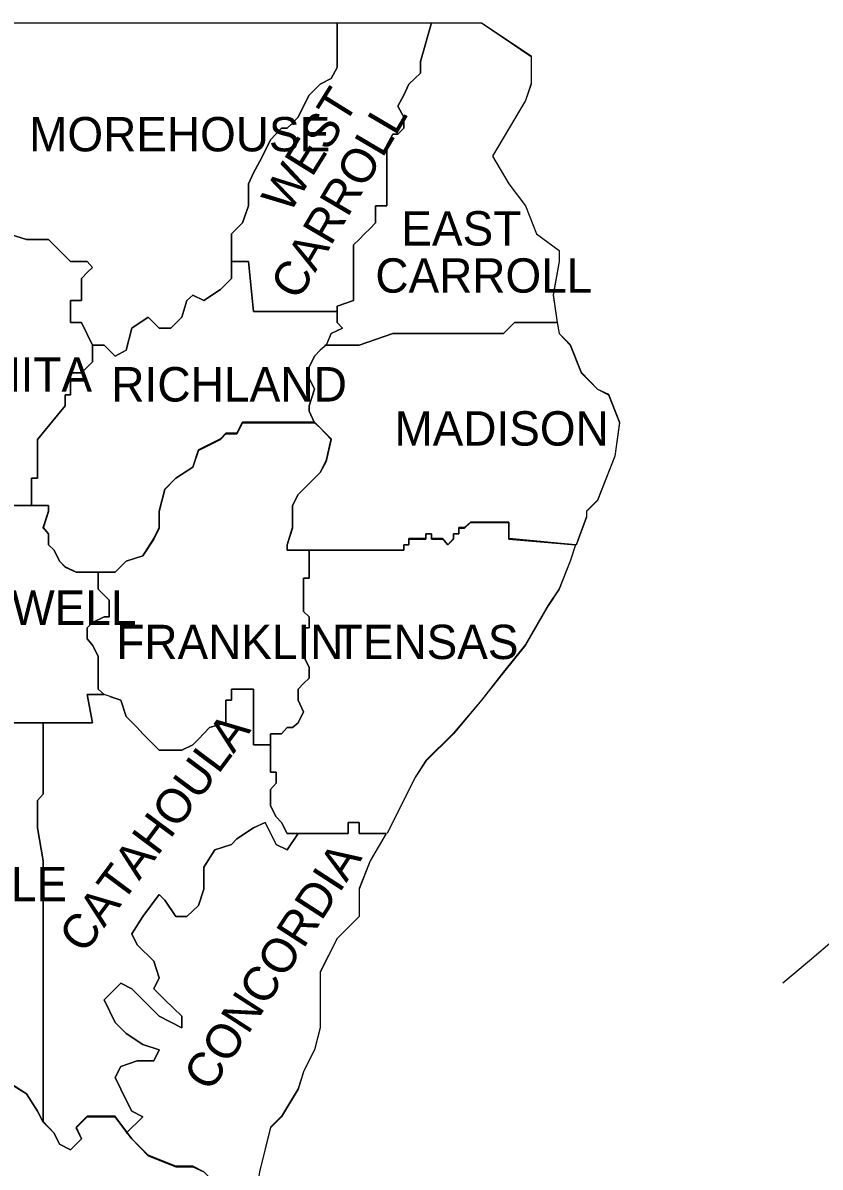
# Model space of a CAD drawing. Extents: x 0.23 to 2.82, y 0.04 to 1.79.
# Drawn here: x 2.3593 to 2.468, y 1.594 to 1.7498 of the extents above; entities that cross this region are included whole.
import ezdxf

# ---------------------------------------------------------------- set-up
doc = ezdxf.new("R2010")
doc.units = 0
for name, color, linetype in [('Annotation', 7, 'Continuous'), ('Dist05', 7, 'Continuous'), ('Dist08', 7, 'Continuous'), ('Dist58', 7, 'Continuous'), ('Standard Info', 7, 'Continuous')]:
    doc.layers.add(name, color=color, linetype=linetype)

msp = doc.modelspace()

# ---------------------------------------------------------------- linework, layer by layer
at = {"layer": 'Annotation'}
msp.add_open_spline([(2.54158, 1.68565), (2.52602, 1.64446), (2.46291, 1.61901), (2.54158, 1.68565), (2.46291, 1.61901)], degree=3, dxfattribs=at)
at = {"layer": 'Dist05'}
for p, q in [((2.35674, 1.74983), (2.40215, 1.74983)), ((2.40215, 1.74983), (2.41499, 1.74983)), ((2.41499, 1.74983), (2.42182, 1.74983))]:
    msp.add_line(p, q, dxfattribs=at)
for points in [[(2.42182, 1.74983), (2.42857, 1.74533), (2.42857, 1.74158), (2.42782, 1.73925), (2.42332, 1.73167), (2.42557, 1.72792), (2.42782, 1.72492), (2.42932, 1.72108), (2.4324, 1.71883), (2.4324, 1.71733), (2.43157, 1.71283), (2.43215, 1.709)], [(2.43215, 1.709), (2.4324, 1.7075), (2.4339, 1.706), (2.4354, 1.70225), (2.43765, 1.69992), (2.43915, 1.69925), (2.44065, 1.69542), (2.43999, 1.69083), (2.43765, 1.68483), (2.43615, 1.68333), (2.43615, 1.68258), (2.43474, 1.67875)], [(2.39907, 1.69542), (2.38924, 1.69542), (2.38849, 1.69392), (2.38699, 1.69392), (2.38624, 1.69317), (2.38324, 1.69167), (2.38249, 1.68933), (2.38015, 1.68783), (2.37865, 1.68633), (2.3779, 1.68333), (2.3779, 1.68108), (2.37715, 1.67958), (2.37565, 1.67725), (2.3734, 1.6765), (2.3719, 1.675), (2.36957, 1.675), (2.36807, 1.675), (2.36657, 1.675), (2.36507, 1.67575), (2.36432, 1.6765), (2.36357, 1.678), (2.36282, 1.67875), (2.36282, 1.68025), (2.36207, 1.68108), (2.36282, 1.68333), (2.36282, 1.68408), (2.36049, 1.68408)], [(2.41124, 1.678), (2.39532, 1.678), (2.39532, 1.67875), (2.39607, 1.68108), (2.39607, 1.68258), (2.39607, 1.68408), (2.39682, 1.68558), (2.39982, 1.68858), (2.40065, 1.69017), (2.40132, 1.69317), (2.39982, 1.69467), (2.39907, 1.69542)], [(2.36049, 1.68408), (2.35524, 1.68408), (2.35449, 1.68333), (2.3514, 1.68333), (2.35074, 1.68408), (2.34015, 1.68408)], [(2.42557, 1.67958), (2.42557, 1.68183), (2.42032, 1.68183), (2.41949, 1.68108), (2.41874, 1.68108), (2.41874, 1.68025), (2.41799, 1.68025), (2.41799, 1.67958), (2.41724, 1.67875), (2.41649, 1.67958), (2.41499, 1.67958), (2.41499, 1.68025), (2.41424, 1.68025), (2.41424, 1.67958), (2.4119, 1.67958), (2.4119, 1.67875), (2.41124, 1.67875), (2.41124, 1.678)], [(2.43465, 1.67875), (2.42557, 1.67958)]]:
    msp.add_lwpolyline(points, dxfattribs=at)
at = {"layer": 'Dist08'}
for points in [[(2.36207, 1.60008), (2.36132, 1.60167), (2.35982, 1.60392), (2.35749, 1.60542), (2.35524, 1.60617), (2.35299, 1.6085), (2.3514, 1.61225), (2.3499, 1.61525), (2.3469, 1.61675), (2.3439, 1.61908), (2.34165, 1.62133), (2.34082, 1.62358), (2.33932, 1.62583), (2.33707, 1.62808), (2.33632, 1.62883), (2.33557, 1.63192), (2.33632, 1.63417), (2.33632, 1.63717), (2.33707, 1.64092), (2.33757, 1.644)], [(2.37349, 1.59875), (2.3719, 1.60092), (2.36807, 1.60092), (2.36657, 1.59942), (2.36732, 1.59783), (2.36582, 1.59633), (2.36432, 1.59708), (2.36357, 1.59858), (2.36207, 1.60017)], [(2.38057, 1.57817), (2.38249, 1.582), (2.38399, 1.5835), (2.38399, 1.5865), (2.38474, 1.5895), (2.38549, 1.59183), (2.38399, 1.59333), (2.38249, 1.59408), (2.38015, 1.59408), (2.3764, 1.59558), (2.37415, 1.59783), (2.37349, 1.59875)]]:
    msp.add_lwpolyline(points, dxfattribs=at)
at = {"layer": 'Dist58'}
msp.add_line((2.43465, 1.67875), (2.43465, 1.67875), dxfattribs=at)
for points in [[(2.36049, 1.68408), (2.36282, 1.68408), (2.36282, 1.68333), (2.36207, 1.68108), (2.36282, 1.68025), (2.36282, 1.67875), (2.36357, 1.678), (2.36432, 1.6765), (2.36507, 1.67575), (2.36657, 1.675), (2.36807, 1.675), (2.36957, 1.675), (2.3719, 1.675), (2.3734, 1.6765), (2.37565, 1.67725), (2.37715, 1.67958), (2.3779, 1.68108), (2.3779, 1.68333), (2.37865, 1.68633), (2.38015, 1.68783), (2.38249, 1.68933), (2.38324, 1.69167), (2.38624, 1.69317), (2.38699, 1.69392), (2.38849, 1.69392), (2.38924, 1.69542), (2.39907, 1.69542)], [(2.39907, 1.69542), (2.39982, 1.69467), (2.40132, 1.69317), (2.40065, 1.69017), (2.39982, 1.68858), (2.39682, 1.68558), (2.39607, 1.68408), (2.39607, 1.68258), (2.39607, 1.68108), (2.39532, 1.67875), (2.39532, 1.678), (2.41124, 1.678)], [(2.34015, 1.68408), (2.35074, 1.68408), (2.3514, 1.68333), (2.35449, 1.68333), (2.35524, 1.68408), (2.36049, 1.68408)], [(2.41124, 1.678), (2.41124, 1.67875), (2.4119, 1.67875), (2.4119, 1.67958), (2.41424, 1.67958), (2.41424, 1.68025), (2.41499, 1.68025), (2.41499, 1.67958), (2.41649, 1.67958), (2.41724, 1.67875), (2.41799, 1.67958), (2.41799, 1.68025), (2.41874, 1.68025), (2.41874, 1.68108), (2.41949, 1.68108), (2.42032, 1.68183), (2.42557, 1.68183), (2.42557, 1.67958)], [(2.42557, 1.67958), (2.43465, 1.67875)], [(2.43465, 1.67875), (2.4339, 1.6765), (2.4324, 1.67275), (2.4309, 1.6705), (2.42782, 1.66517), (2.42482, 1.66142), (2.42182, 1.65758), (2.41799, 1.65308), (2.41424, 1.64933), (2.41274, 1.647), (2.40899, 1.63942)], [(2.36207, 1.60008), (2.36132, 1.60167), (2.35982, 1.60392), (2.35749, 1.60542), (2.35524, 1.60617), (2.35299, 1.6085), (2.3514, 1.61225), (2.3499, 1.61525), (2.3469, 1.61675), (2.3439, 1.61908), (2.34165, 1.62133), (2.34082, 1.62358), (2.33932, 1.62583), (2.33707, 1.62808), (2.33632, 1.62883), (2.33557, 1.63192), (2.33632, 1.63417), (2.33632, 1.63717), (2.33707, 1.64092), (2.33757, 1.644)], [(2.40882, 1.63942), (2.40665, 1.63567), (2.40515, 1.63192), (2.40515, 1.62808), (2.40215, 1.62508), (2.39982, 1.62058), (2.39982, 1.613), (2.39907, 1.61), (2.39757, 1.60692), (2.39682, 1.60467), (2.39457, 1.60092), (2.39307, 1.59942), (2.39157, 1.59333), (2.39074, 1.588), (2.39157, 1.58425), (2.39232, 1.58275), (2.39382, 1.57975)], [(2.37349, 1.59875), (2.3719, 1.60092), (2.36807, 1.60092), (2.36657, 1.59942), (2.36732, 1.59783), (2.36582, 1.59633), (2.36432, 1.59708), (2.36357, 1.59858), (2.36207, 1.60017)], [(2.38057, 1.57817), (2.38249, 1.582), (2.38399, 1.5835), (2.38399, 1.5865), (2.38474, 1.5895), (2.38549, 1.59183), (2.38399, 1.59333), (2.38249, 1.59408), (2.38015, 1.59408), (2.3764, 1.59558), (2.37415, 1.59783), (2.37349, 1.59875)]]:
    msp.add_lwpolyline(points, dxfattribs=at)
at = {"layer": 'Standard Info'}
for p, q in [((2.35674, 1.74983), (2.40215, 1.74983)), ((2.40215, 1.74983), (2.41499, 1.74983)), ((2.41499, 1.74983), (2.42182, 1.74983)), ((2.40057, 1.70592), (2.40049, 1.70592))]:
    msp.add_line(p, q, dxfattribs=at)
for points in [[(2.38774, 1.71733), (2.38774, 1.71883), (2.38774, 1.72108), (2.38849, 1.72183), (2.38924, 1.72258), (2.39007, 1.72492), (2.39007, 1.72792), (2.39074, 1.72942), (2.39157, 1.73092), (2.39232, 1.73242), (2.39307, 1.73392), (2.39457, 1.7355), (2.39532, 1.7355), (2.39607, 1.73617), (2.39682, 1.737), (2.39757, 1.7385), (2.39832, 1.74), (2.39982, 1.7415), (2.40132, 1.74225), (2.40215, 1.74375), (2.40215, 1.74458), (2.40215, 1.74983)], [(2.40215, 1.74983), (2.40215, 1.74458), (2.40215, 1.74375), (2.40132, 1.74225), (2.39982, 1.7415), (2.39832, 1.74), (2.39757, 1.7385), (2.39682, 1.737), (2.39607, 1.73617), (2.39532, 1.7355), (2.39457, 1.7355), (2.39307, 1.73392), (2.39232, 1.73242), (2.39157, 1.73092), (2.39074, 1.72942), (2.39007, 1.72792), (2.39007, 1.72492), (2.38924, 1.72258), (2.38849, 1.72183), (2.38774, 1.72108), (2.38774, 1.71883), (2.38774, 1.71733)], [(2.38774, 1.71733), (2.38774, 1.71883), (2.38774, 1.72108), (2.38849, 1.72183), (2.38924, 1.72258), (2.39007, 1.72492), (2.39007, 1.72792), (2.39074, 1.72942), (2.39157, 1.73092), (2.39232, 1.73242), (2.39307, 1.73392), (2.39457, 1.7355), (2.39532, 1.7355), (2.39607, 1.73617), (2.39682, 1.737), (2.39757, 1.7385), (2.39832, 1.74), (2.39982, 1.7415), (2.40132, 1.74225), (2.40215, 1.74375), (2.40215, 1.74458), (2.40215, 1.74983)], [(2.40074, 1.70608), (2.40132, 1.7075), (2.4029, 1.70825), (2.40215, 1.709), (2.40215, 1.7105), (2.40215, 1.71125), (2.4044, 1.712), (2.4044, 1.71275), (2.4044, 1.7135), (2.4044, 1.71433), (2.4044, 1.71583), (2.4044, 1.71733), (2.4044, 1.71958), (2.40515, 1.72033), (2.4059, 1.72108), (2.40665, 1.72183), (2.4074, 1.72258), (2.4074, 1.72492), (2.4089, 1.72492), (2.4089, 1.73317), (2.40974, 1.73467), (2.4104, 1.73467), (2.41124, 1.7355), (2.41124, 1.737), (2.4104, 1.7385), (2.41124, 1.74), (2.4119, 1.7415), (2.41274, 1.74225), (2.41349, 1.743), (2.41349, 1.74458), (2.41499, 1.74983)], [(2.41499, 1.74983), (2.41349, 1.74458), (2.41349, 1.743), (2.41274, 1.74225), (2.4119, 1.7415), (2.41124, 1.74), (2.4104, 1.7385), (2.41124, 1.737), (2.41124, 1.7355), (2.4104, 1.73467), (2.40974, 1.73467), (2.4089, 1.73317), (2.4089, 1.72492), (2.4074, 1.72492), (2.4074, 1.72258), (2.40665, 1.72183), (2.4059, 1.72108), (2.40515, 1.72033), (2.4044, 1.71958), (2.4044, 1.71733), (2.4044, 1.71583), (2.4044, 1.71433), (2.4044, 1.7135), (2.4044, 1.71275), (2.4044, 1.712), (2.40215, 1.71125), (2.40215, 1.7105)], [(2.42182, 1.74983), (2.42857, 1.74525), (2.42857, 1.7415), (2.42782, 1.73925), (2.42332, 1.73167), (2.42557, 1.72792), (2.42782, 1.72492), (2.42932, 1.72108), (2.4324, 1.71883), (2.4324, 1.71733), (2.43157, 1.71275), (2.43215, 1.709)], [(2.3569, 1.72125), (2.35982, 1.72033), (2.36282, 1.72033), (2.36432, 1.71883), (2.36582, 1.71733), (2.36807, 1.71733), (2.36882, 1.7165), (2.36807, 1.71583), (2.36732, 1.715), (2.36732, 1.712), (2.36582, 1.712), (2.36582, 1.709), (2.36732, 1.709), (2.36882, 1.70592), (2.36882, 1.70367), (2.36732, 1.70217), (2.36582, 1.70217), (2.36582, 1.69917), (2.36507, 1.69917), (2.36507, 1.69767), (2.36132, 1.69308), (2.36132, 1.68783), (2.36049, 1.68783), (2.36049, 1.68408)], [(2.36882, 1.70592), (2.36732, 1.709), (2.36582, 1.709), (2.36582, 1.712), (2.36732, 1.712), (2.36732, 1.715), (2.36807, 1.71583), (2.36882, 1.7165), (2.36807, 1.71733), (2.36582, 1.71733), (2.36432, 1.71883), (2.36282, 1.72033), (2.35982, 1.72033), (2.3569, 1.72125)], [(2.38774, 1.71733), (2.38774, 1.715), (2.38624, 1.7135), (2.38399, 1.712), (2.38249, 1.71275), (2.38165, 1.712), (2.38099, 1.70975), (2.37949, 1.70825), (2.3779, 1.70825), (2.3764, 1.70975), (2.37415, 1.70825), (2.3734, 1.70525), (2.3719, 1.70442), (2.3704, 1.70592), (2.36882, 1.70592)], [(2.36882, 1.70592), (2.3704, 1.70592), (2.3719, 1.70442), (2.3734, 1.70525), (2.37415, 1.70825), (2.3764, 1.70975), (2.3779, 1.70825), (2.37949, 1.70825), (2.38099, 1.70975), (2.38165, 1.712), (2.38249, 1.71275), (2.38399, 1.712), (2.38624, 1.7135), (2.38774, 1.715), (2.38774, 1.71733)], [(2.40215, 1.7105), (2.39074, 1.7105), (2.39007, 1.71733), (2.38774, 1.71733)], [(2.38774, 1.71733), (2.39007, 1.71733), (2.39074, 1.7105), (2.40215, 1.7105)], [(2.40215, 1.7105), (2.40215, 1.709), (2.4029, 1.70825), (2.40132, 1.7075), (2.40065, 1.70592), (2.39982, 1.70525), (2.39907, 1.70442), (2.39832, 1.70292), (2.39832, 1.70217), (2.39832, 1.70142), (2.39907, 1.69992), (2.39832, 1.69767), (2.39832, 1.69692), (2.39907, 1.69533)], [(2.43215, 1.709), (2.42632, 1.709), (2.42482, 1.7075), (2.40974, 1.7075), (2.40515, 1.70592), (2.40049, 1.70592)], [(2.40049, 1.70592), (2.40515, 1.70592), (2.40974, 1.7075), (2.42482, 1.7075), (2.42632, 1.709), (2.43215, 1.709)], [(2.43215, 1.709), (2.4324, 1.7075), (2.4339, 1.70592), (2.4354, 1.70217), (2.43765, 1.69992), (2.43915, 1.69917), (2.44065, 1.69533), (2.43999, 1.69083), (2.43765, 1.68475), (2.43615, 1.68325), (2.43615, 1.6825), (2.43474, 1.67867)], [(2.36049, 1.68408), (2.36049, 1.68783), (2.36132, 1.68783), (2.36132, 1.69308), (2.36507, 1.69767), (2.36507, 1.69917), (2.36582, 1.69917), (2.36582, 1.70217), (2.36732, 1.70217), (2.36882, 1.70367), (2.36882, 1.70592)], [(2.39907, 1.69533), (2.39832, 1.69692), (2.39832, 1.69767), (2.39907, 1.69992), (2.39832, 1.70142), (2.39832, 1.70217), (2.39832, 1.70292), (2.39907, 1.70442), (2.39982, 1.70525), (2.40057, 1.70592)], [(2.39907, 1.69533), (2.38924, 1.69533), (2.38849, 1.69383), (2.38699, 1.69383), (2.38624, 1.69308), (2.38324, 1.69158), (2.38249, 1.68933), (2.38015, 1.68783), (2.37865, 1.68625), (2.3779, 1.68325), (2.3779, 1.681), (2.37715, 1.6795), (2.37565, 1.67725), (2.3734, 1.6765), (2.3719, 1.675), (2.36957, 1.675), (2.36807, 1.675), (2.36657, 1.675), (2.36507, 1.67567), (2.36432, 1.6765), (2.36357, 1.678), (2.36282, 1.67875), (2.36282, 1.68025), (2.36207, 1.681), (2.36282, 1.68325), (2.36282, 1.68408), (2.36049, 1.68408)], [(2.36957, 1.675), (2.3719, 1.675), (2.3734, 1.6765), (2.37565, 1.67725), (2.37715, 1.6795), (2.3779, 1.681), (2.3779, 1.68325), (2.37865, 1.68625), (2.38015, 1.68783), (2.38249, 1.68933), (2.38324, 1.69158), (2.38624, 1.69308), (2.38699, 1.69383), (2.38849, 1.69383), (2.38924, 1.69533), (2.39907, 1.69533)], [(2.41124, 1.678), (2.39532, 1.678), (2.39532, 1.67875), (2.39607, 1.681), (2.39607, 1.6825), (2.39607, 1.68408), (2.39682, 1.68558), (2.39982, 1.68858), (2.40065, 1.69008), (2.40132, 1.69308), (2.39982, 1.69467), (2.39907, 1.69533)], [(2.39907, 1.69533), (2.39982, 1.69467), (2.40132, 1.69308), (2.40065, 1.69008), (2.39982, 1.68858), (2.39682, 1.68558), (2.39607, 1.68408), (2.39607, 1.6825), (2.39607, 1.681), (2.39532, 1.67875), (2.39532, 1.678), (2.39832, 1.678)], [(2.36049, 1.68408), (2.35524, 1.68408), (2.35449, 1.68325), (2.3514, 1.68325), (2.35074, 1.68408), (2.34015, 1.68408)], [(2.34015, 1.68408), (2.35074, 1.68408), (2.3514, 1.68325), (2.35449, 1.68325), (2.35524, 1.68408), (2.36282, 1.68408), (2.36282, 1.68325), (2.36207, 1.681), (2.36282, 1.68025), (2.36282, 1.67875), (2.36357, 1.678), (2.36432, 1.6765), (2.36507, 1.67567), (2.36657, 1.675), (2.36807, 1.675), (2.36957, 1.675)], [(2.42557, 1.6795), (2.42557, 1.68175), (2.42032, 1.68175), (2.41949, 1.681), (2.41874, 1.681), (2.41874, 1.68025), (2.41799, 1.68025), (2.41799, 1.6795), (2.41724, 1.67875), (2.41649, 1.6795), (2.41499, 1.6795), (2.41499, 1.68025), (2.41424, 1.68025), (2.41424, 1.6795), (2.4119, 1.6795), (2.4119, 1.67875), (2.41124, 1.67875), (2.41124, 1.678)], [(2.41124, 1.678), (2.41124, 1.67875), (2.4119, 1.67875), (2.4119, 1.6795), (2.41424, 1.6795), (2.41424, 1.68025), (2.41499, 1.68025), (2.41499, 1.6795), (2.41649, 1.6795), (2.41724, 1.67875), (2.41799, 1.6795), (2.41799, 1.68025), (2.41874, 1.68025), (2.41874, 1.681), (2.41949, 1.681), (2.42032, 1.68175), (2.42557, 1.68175), (2.42557, 1.6795)], [(2.43465, 1.67875), (2.42557, 1.6795)], [(2.42557, 1.6795), (2.43465, 1.67875)], [(2.39832, 1.678), (2.39832, 1.67417), (2.39757, 1.67417), (2.39757, 1.66967), (2.39832, 1.66892), (2.39832, 1.66742), (2.39757, 1.66742), (2.39757, 1.66358), (2.39832, 1.66208), (2.39832, 1.66058), (2.39757, 1.65983), (2.39682, 1.65908), (2.39682, 1.65758), (2.39757, 1.656), (2.39682, 1.6545), (2.39607, 1.65383), (2.39532, 1.65383), (2.39457, 1.653), (2.39307, 1.653), (2.39307, 1.6515)], [(2.40882, 1.63942), (2.40515, 1.63942), (2.40515, 1.64092), (2.40365, 1.64092), (2.40365, 1.63942), (2.40215, 1.63942), (2.39757, 1.63942), (2.39532, 1.63942), (2.39457, 1.64092), (2.39382, 1.64167), (2.39307, 1.64317), (2.39307, 1.64392), (2.39307, 1.64542), (2.39382, 1.64625), (2.39382, 1.64775), (2.39307, 1.64775), (2.39307, 1.653), (2.39457, 1.653), (2.39532, 1.65383), (2.39607, 1.65383), (2.39682, 1.6545), (2.39757, 1.656), (2.39682, 1.65758), (2.39682, 1.65908), (2.39757, 1.65983), (2.39832, 1.66058), (2.39832, 1.66208), (2.39757, 1.66358), (2.39757, 1.66742), (2.39832, 1.66742), (2.39832, 1.66892), (2.39757, 1.66967), (2.39757, 1.67417), (2.39832, 1.67417), (2.39832, 1.678)], [(2.39832, 1.678), (2.41124, 1.678)], [(2.43465, 1.67875), (2.4339, 1.6765), (2.4324, 1.67267), (2.4309, 1.67042), (2.42782, 1.66508), (2.42482, 1.66133), (2.42182, 1.65758), (2.41799, 1.653), (2.41424, 1.64925), (2.41274, 1.647), (2.40899, 1.63942)], [(2.36957, 1.675), (2.36957, 1.67267), (2.37107, 1.67117), (2.37107, 1.66892), (2.3704, 1.66892), (2.36882, 1.66817), (2.36807, 1.66742), (2.36807, 1.66592), (2.36882, 1.66508), (2.36957, 1.66358), (2.36957, 1.66133), (2.36957, 1.65908), (2.3704, 1.65833)], [(2.39307, 1.6515), (2.39074, 1.6515), (2.39074, 1.65908), (2.38774, 1.65908), (2.38774, 1.65758), (2.38699, 1.65758), (2.38699, 1.656), (2.38699, 1.6545), (2.38474, 1.65383), (2.38324, 1.65225), (2.38249, 1.6515), (2.38099, 1.65075), (2.37949, 1.65075), (2.3779, 1.65075), (2.37715, 1.6515), (2.37565, 1.653), (2.3749, 1.65383), (2.3734, 1.65533), (2.37265, 1.65758), (2.3704, 1.65833), (2.36957, 1.65908), (2.36957, 1.66133), (2.36957, 1.66358), (2.36882, 1.66508), (2.36807, 1.66592), (2.36807, 1.66742), (2.36882, 1.66817), (2.3704, 1.66892), (2.37107, 1.66892), (2.37107, 1.67117), (2.36957, 1.67267), (2.36957, 1.675)], [(2.37115, 1.65808), (2.37265, 1.65758), (2.3734, 1.65533), (2.3749, 1.65383), (2.37565, 1.653), (2.37715, 1.6515), (2.3779, 1.65075), (2.37949, 1.65075), (2.38099, 1.65075), (2.38249, 1.6515), (2.38324, 1.65225), (2.38474, 1.65383), (2.38699, 1.6545), (2.38699, 1.656), (2.38699, 1.65758), (2.38774, 1.65758), (2.38774, 1.65908), (2.39074, 1.65908), (2.39074, 1.6515), (2.39307, 1.6515)], [(2.3704, 1.65833), (2.36807, 1.65833), (2.36882, 1.6545), (2.36207, 1.6545), (2.34015, 1.6545)], [(2.36207, 1.6545), (2.36882, 1.6545), (2.36807, 1.65833), (2.3704, 1.65833)], [(2.34015, 1.6545), (2.36207, 1.6545)], [(2.36207, 1.6545), (2.36207, 1.64475), (2.36132, 1.64392), (2.36132, 1.64017), (2.36207, 1.63567), (2.36207, 1.60008)], [(2.36207, 1.60008), (2.36207, 1.63567), (2.36132, 1.64017), (2.36132, 1.64392), (2.36207, 1.64475), (2.36207, 1.6545)], [(2.39307, 1.6515), (2.39307, 1.64775), (2.39382, 1.64775), (2.39382, 1.64625), (2.39307, 1.64542), (2.39307, 1.64392), (2.39307, 1.64317), (2.39382, 1.64167), (2.39457, 1.64092), (2.39532, 1.63942), (2.39682, 1.63942)], [(2.36207, 1.60008), (2.36132, 1.60158), (2.35982, 1.60392), (2.35749, 1.60542), (2.35524, 1.60617), (2.35299, 1.60842), (2.3514, 1.61217), (2.3499, 1.61517), (2.3469, 1.61675), (2.3439, 1.619), (2.34165, 1.62125), (2.34082, 1.62358), (2.33932, 1.62575), (2.33707, 1.62808), (2.33632, 1.62883), (2.33557, 1.63183), (2.33632, 1.63417), (2.33632, 1.63717), (2.33707, 1.64092), (2.33757, 1.64392)], [(2.39682, 1.63942), (2.39532, 1.63717), (2.39382, 1.63792), (2.39232, 1.64092), (2.39074, 1.64017), (2.38849, 1.63867), (2.38774, 1.63792), (2.38549, 1.63717), (2.38399, 1.63483), (2.38399, 1.63333), (2.38399, 1.63183), (2.38324, 1.62958), (2.38165, 1.62808), (2.38015, 1.62808), (2.37865, 1.63033), (2.3779, 1.63108), (2.37565, 1.62808), (2.37415, 1.62575), (2.3749, 1.62425), (2.37715, 1.622), (2.3779, 1.61975), (2.37715, 1.61825), (2.37865, 1.61675), (2.38099, 1.6145), (2.38099, 1.61292), (2.3779, 1.6145), (2.37565, 1.61675), (2.37415, 1.61825), (2.37265, 1.619), (2.3704, 1.61675), (2.3719, 1.61367), (2.3734, 1.61217), (2.37565, 1.61067), (2.3779, 1.60992), (2.37715, 1.60842), (2.3749, 1.60842), (2.37265, 1.60767), (2.3719, 1.60617), (2.37265, 1.60458), (2.3734, 1.60308), (2.37415, 1.60158), (2.37565, 1.60083), (2.3734, 1.59858)], [(2.3734, 1.59858), (2.37565, 1.60083), (2.37415, 1.60158), (2.3734, 1.60308), (2.37265, 1.60458), (2.3719, 1.60617), (2.37265, 1.60767), (2.3749, 1.60842), (2.37715, 1.60842), (2.3779, 1.60992), (2.37565, 1.61067), (2.3734, 1.61217), (2.3719, 1.61367), (2.3704, 1.61675), (2.37265, 1.619), (2.37415, 1.61825), (2.37565, 1.61675), (2.3779, 1.6145), (2.38099, 1.61292), (2.38099, 1.6145), (2.37865, 1.61675), (2.37715, 1.61825), (2.3779, 1.61975), (2.37715, 1.622), (2.3749, 1.62425), (2.37415, 1.62575), (2.37565, 1.62808), (2.3779, 1.63108), (2.37865, 1.63033), (2.38015, 1.62808), (2.38165, 1.62808), (2.38324, 1.62958), (2.38399, 1.63183), (2.38399, 1.63333), (2.38399, 1.63483), (2.38549, 1.63717), (2.38774, 1.63792), (2.38849, 1.63867), (2.39074, 1.64017), (2.39232, 1.64092), (2.39382, 1.63792), (2.39532, 1.63717), (2.39682, 1.63942)], [(2.39682, 1.63942), (2.40215, 1.63942), (2.40365, 1.63942), (2.40365, 1.64092), (2.40515, 1.64092), (2.40515, 1.63942), (2.40882, 1.63942)], [(2.40882, 1.63942), (2.40665, 1.63567), (2.40515, 1.63183), (2.40515, 1.62808), (2.40215, 1.62508), (2.39982, 1.6205), (2.39982, 1.61292), (2.39907, 1.60992), (2.39757, 1.60692), (2.39682, 1.60458), (2.39457, 1.60083), (2.39307, 1.59933), (2.39157, 1.59333), (2.39074, 1.588), (2.39157, 1.58425), (2.39232, 1.58267), (2.39382, 1.57967)], [(2.35815, 1.605), (2.35982, 1.60392), (2.36132, 1.60158), (2.36207, 1.60008), (2.36357, 1.59858), (2.36432, 1.59708), (2.36582, 1.59633), (2.36732, 1.59783), (2.36657, 1.59933), (2.36807, 1.60083), (2.3719, 1.60083), (2.37415, 1.59783), (2.3764, 1.5955), (2.38015, 1.594), (2.38249, 1.594), (2.38399, 1.59333), (2.38549, 1.59175), (2.38474, 1.5895), (2.38399, 1.5865), (2.38399, 1.58342), (2.38249, 1.58192), (2.38065, 1.57833)], [(2.37349, 1.59867), (2.3719, 1.60083), (2.36807, 1.60083), (2.36657, 1.59933), (2.36732, 1.59783), (2.36582, 1.59633), (2.36432, 1.59708), (2.36357, 1.59858), (2.36207, 1.60017)], [(2.38057, 1.57817), (2.38249, 1.58192), (2.38399, 1.58342), (2.38399, 1.5865), (2.38474, 1.5895), (2.38549, 1.59175), (2.38399, 1.59333), (2.38249, 1.594), (2.38015, 1.594), (2.3764, 1.5955), (2.37415, 1.59783), (2.37349, 1.59867)]]:
    msp.add_lwpolyline(points, dxfattribs=at)

# ---------------------------------------------------------------- texts
for s, rotation, p in [('WEST', 58.1411, (2.3956, 1.72366)), ('CARROLL', 59.4887, (2.39686, 1.71184)), ('CATAHOULA', 53.3344, (2.36768, 1.62284)), ('CONCORDIA', 57.0945, (2.38489, 1.60403))]:
    msp.add_text(s, height=0.004679, rotation=rotation, dxfattribs=at).set_placement(p)
for s, height, p in [('MOREHOUSE', 0.004679, (2.36018, 1.73233)), ('EAST', 0.004679, (2.4109, 1.7195)), ('CARROLL', 0.004679, (2.40736, 1.71308)), ('OUACHITA', 0.004679, (2.33642, 1.69958)), ('RICHLAND', 0.0047, (2.37136, 1.69825)), ('MADISON', 0.004679, (2.40996, 1.69225)), ('CALDWELL', 0.004679, (2.34106, 1.66783)), ('TENSAS', 0.004679, (2.40183, 1.66317)), ('FRANKLIN', 0.004679, (2.37206, 1.66316)), ('LASALLE', 0.004679, (2.33822, 1.63017))]:
    msp.add_text(s, height=height, dxfattribs=at).set_placement(p)

doc.saveas('drawing.dxf')
